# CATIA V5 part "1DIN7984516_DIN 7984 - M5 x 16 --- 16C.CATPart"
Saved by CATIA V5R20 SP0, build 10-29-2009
Part number: 1DIN7984516_DIN 7984 - M5 x 16 --- 16C
Revision: ANY
Definition: UNKNOWN
Nomenclature: 1DIN7984516_DIN 7984 - M5 x 16 --- 16C
Source: Unknown
Bounding box of the stored display mesh (mm): x 0 to 19.5, y -4.25 to 4.25, z -4.25 to 4.25
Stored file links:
  C:\Users\Utente\Desktop\IO LAVORO\3D X SITO CF\CUMSA\3D files PW\pw081025\pw081025_ejection\1DIN7984516_DIN 7984 - M5 x 16 --- 16C.CATPart
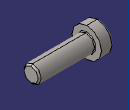
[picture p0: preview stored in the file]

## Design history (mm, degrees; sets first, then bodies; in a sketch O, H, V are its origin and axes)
Body1 "Hex" (main body)
  Solid1: solid without history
